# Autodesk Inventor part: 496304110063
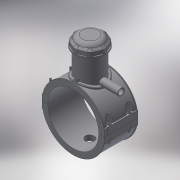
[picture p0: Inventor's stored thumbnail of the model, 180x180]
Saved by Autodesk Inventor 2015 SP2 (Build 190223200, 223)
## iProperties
Created: 2017-07
Part Number: 496304110063
Material: Generic
Description: PLASSON TAPPING SADDLE 110x63
Document SubType Name: Modeling
Designer: KIM
Mass: 993.448 g
Surface Area: 2313.51 cm^2
Volume: 993.448 cm^3
Density: 1 g/cm^3
Appearance: Default
Author: KIM
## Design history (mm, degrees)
derived "496304.ipt"
feature "Solid1::496304.ipt"
feature "Solid2::496304.ipt"
feature "Solid4::496304.ipt"
feature "Solid5::496304.ipt"
tag "TaggingFeature1"
body "Solid1"
body "Solid2"
other parameters: "d2" = 148, "d3" = 27.5, "d4" = 118, "d5" = 0, "d6" = 0.1, "d8" = 0, "d19" = 6, "d20" = 6, "d21" = 70.8, "d23" = 0, "d24" = 35.4, "d26" = 0, "d29" = 3, "d30" = 36.66667, "d31" = 6, "d32" = 0, "d33" = 0, "d34" = 0.6, "d40" = 68.64, "d41" = 74.8, "d43" = 0, "d45" = 0, "d47" = 136.8, "d70" = 15, "d72" = 0, "d73" = 6, "d75" = 5, "d76" = 0, "d77" = 5.5, "d78" = 85, "d79" = 15, "d80" = 47.2, "d82" = 5 deg, "d84" = 4, "d85" = 14, "d86" = 0, "d87" = 3, "d88" = 0, "d89" = 1, "d90" = 1, "d91" = 94.4, "d92" = 0, "d93" = 0.5, "d94" = 57.89474, "d96" = 134.64, "d97" = 2.36, "d98" = 0, "d102" = 1.1, "d120" = 140 deg, "d121" = 24.228, "d122" = 20 deg, "d123" = 264, "d124" = 79.2, "d126" = 0, "d143" = 113.3, "d145" = 16.92308, "d149" = 1.65, "d150" = 18.61538, "d153" = 118, "d154" = 0, "d156" = 66, "d157" = 160 deg, "d159" = 4.4, "d161" = 1.65, "d162" = 70.8, "d163" = 0, "d164" = 55, "d167" = 11, "d168" = 64.39024, "d170" = 3.375, "d172" = 0, "d173" = 1, "d175" = 55, "d176" = 20 deg, "d177" = 7.7, "d178" = 22, "d180" = 0, "d183" = 8.8, "d184" = 6.16, "d185" = 38.35, "d186" = 38.35, "d187" = 66, "d188" = 6.6, "d189" = 7.7, "d190" = 0, "d191" = 99, "d193" = 6.3, "d194" = 4.13, "d195" = 90 deg, "d197" = 0, "d199" = 0, "d200" = 11, "d202" = 0, "d203" = 177, "d204" = 71.06, "d205" = 52.36, "d206" = 63.58, "d207" = 132.75, "d208" = 138.06, "d209" = 164.61, "d210" = 64.328, "d211" = 74.8, "d212" = 59.84, "d213" = 29.25, "d216" = 0, "d217" = 11, "d218" = 11, "d219" = 2.2, "d224" = 0, "d230" = 4.4, "d233" = 6, "d236" = 74, "d237" = 35.4, "d238" = 6.02433, "d240" = 35.4, "d241" = 35.4, "d242" = 35.4, "d243" = 6, "d244" = 35.4, "d245" = 35.4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
